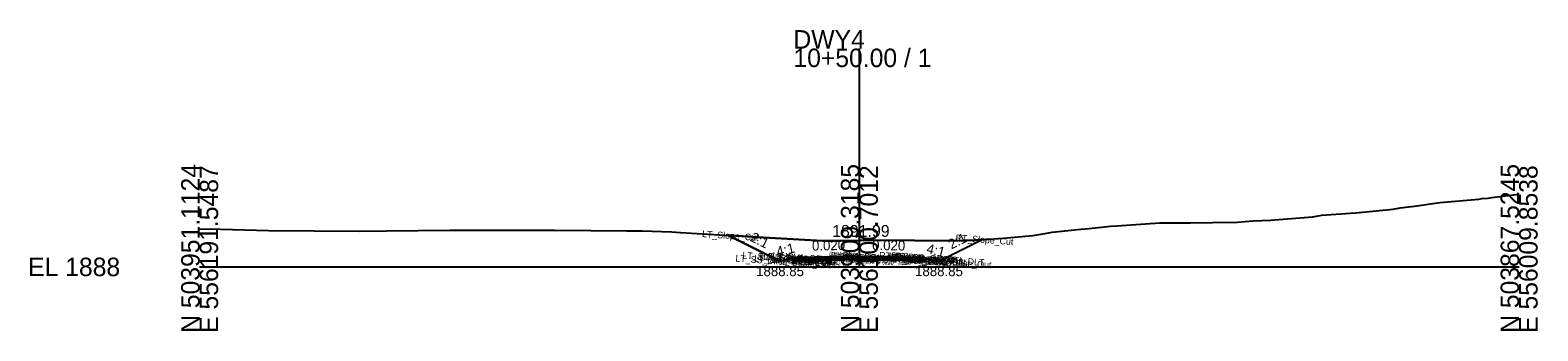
# Model space of a CAD drawing. Extents: x -26 to 556133, y -10 to 503926.
# Drawn here: x -25.7 to 202.8, y 490.3 to 535.9 of the extents above; entities that cross this region are included whole.
import ezdxf

# ---------------------------------------------------------------- set-up
doc = ezdxf.new("R2010")
doc.units = 0
for name, color, linetype in [('Default', 7, 'Continuous'), ('Exist Cross Section Cell', 7, 'Continuous'), ('Exist XS Center Line Elevation Label', 7, 'Continuous'), ('Exist XS Ground Line', 7, 'Continuous'), ('Prop CMT Pvmt Course 1', 7, 'Continuous'), ('Prop CMT Pvmt Course 2', 7, 'Continuous'), ('Prop CMT Pvmt Surface', 7, 'Continuous'), ('Prop CMT Shld Paved Course 1', 7, 'Continuous'), ('Prop CMT Shld Paved Course 2', 7, 'Continuous'), ('Prop CMT Slope Grass', 7, 'Continuous'), ('Prop CMT Subgrade Earthwork', 7, 'Continuous'), ('Prop XS Ditch Standard Text', 7, 'Continuous'), ('Prop XS Earthwork Shape', 7, 'Continuous'), ('Prop XS SE Text', 7, 'Continuous'), ('Prop XS Side Slope Text', 7, 'Continuous'), ('Typical Text Centerline CELL', 7, 'Continuous')]:
    doc.layers.add(name, color=color, linetype=linetype)

msp = doc.modelspace()

# ---------------------------------------------------------------- linework, layer by layer
at = {"layer": 'Exist Cross Section Cell'}
for p, q in [((100, 500), (100, 533.09)), ((0, 500), (100, 500)), ((100, 500), (200, 500))]:
    msp.add_line(p, q, dxfattribs=at)
at = {"layer": 'Exist XS Ground Line'}
for p, q in [((184.12, 509.19), (187.97, 509.76)), ((187.97, 509.76), (193.89, 510.29)), ((193.89, 510.29), (194.35, 510.35)), ((194.35, 510.35), (195.31, 510.43)), ((195.31, 510.43), (195.84, 510.5)), ((195.84, 510.5), (198.31, 510.84)), ((198.31, 510.84), (200, 511.03)), ((164.86, 507.3), (168.73, 507.61)), ((168.73, 507.61), (170.08, 507.83)), ((170.08, 507.83), (174.4, 508.16)), ((174.4, 508.16), (175.25, 508.22)), ((175.25, 508.22), (180.92, 508.77)), ((180.92, 508.77), (181.98, 508.98)), ((181.98, 508.98), (184.12, 509.19)), ((0, 505.76), (3.14, 505.72)), ((3.14, 505.72), (10.42, 505.52)), ((10.42, 505.52), (24.29, 505.44)), ((24.29, 505.44), (28.36, 505.46)), ((28.36, 505.46), (37.92, 505.58)), ((37.92, 505.58), (42.39, 505.58)), ((42.39, 505.58), (53.86, 505.55)), ((53.86, 505.55), (64.73, 505.46)), ((64.73, 505.46), (67.05, 505.46)), ((67.05, 505.46), (71.58, 505.3)), ((71.58, 505.3), (72.89, 505.24)), ((72.89, 505.24), (85.47, 504.46)), ((126.29, 504.74), (128.41, 505.13)), ((128.41, 505.13), (129.2, 505.25)), ((129.2, 505.25), (133.57, 505.7)), ((133.57, 505.7), (134.85, 505.83)), ((134.85, 505.83), (138.06, 506.16)), ((138.06, 506.16), (139.04, 506.23)), ((139.04, 506.23), (145.55, 506.67)), ((145.55, 506.67), (150.18, 506.69)), ((150.18, 506.69), (153.52, 506.72)), ((153.52, 506.72), (157.31, 506.8)), ((157.31, 506.8), (159.64, 506.98)), ((159.64, 506.98), (162.36, 507.1)), ((162.36, 507.1), (164.86, 507.3)), ((85.47, 504.46), (94.39, 503.93)), ((94.39, 503.93), (97.2, 503.95)), ((97.2, 503.95), (100, 503.99)), ((100, 503.99), (102.43, 504.03)), ((102.43, 504.03), (114.33, 503.97)), ((114.33, 503.97), (117.41, 504.05)), ((117.41, 504.05), (121.85, 504.38)), ((121.85, 504.38), (126.29, 504.74))]:
    msp.add_line(p, q, dxfattribs=at)
at = {"layer": 'Prop CMT Pvmt Course 1'}
for points in [[(100, 501.61), (90.95, 501.43)], [(90.95, 501.43), (90.95, 501.18)], [(90.95, 501.18), (100, 501.36)], [(100, 501.36), (100, 501.61)], [(100, 501.61), (109.05, 501.43)], [(100, 501.36), (100, 501.61)], [(109.05, 501.18), (100, 501.36)], [(109.05, 501.43), (109.05, 501.18)]]:
    msp.add_lwpolyline(points, dxfattribs=at)
msp.add_lwpolyline([(100, 501.36), (100, 501.48), (100, 501.48), (100, 501.36)], close=True, dxfattribs=at)
msp.add_lwpolyline([(100, 501.36), (100, 501.48), (100, 501.48), (100, 501.36)], close=True, dxfattribs=at)
at = {"layer": 'Prop CMT Pvmt Course 2'}
for points in [[(100, 501.36), (90.95, 501.18)], [(90.95, 501.18), (90.95, 500.93)], [(90.95, 500.93), (100, 501.11)], [(100, 501.11), (100, 501.36)], [(100, 501.11), (100, 501.36)], [(100, 501.36), (109.05, 501.18)], [(109.05, 500.93), (100, 501.11)], [(109.05, 501.18), (109.05, 500.93)]]:
    msp.add_lwpolyline(points, dxfattribs=at)
at = {"layer": 'Prop CMT Pvmt Surface'}
for points in [[(100, 501.61), (90.95, 501.43)], [(100, 501.61), (109.05, 501.43)]]:
    msp.add_lwpolyline(points, dxfattribs=at)
at = {"layer": 'Prop CMT Shld Paved Course 1'}
for points in [[(90.95, 501.43), (90.7, 501.17)], [(90.7, 501.17), (90.95, 501.18)], [(90.95, 501.18), (90.95, 501.43)], [(109.05, 501.43), (109.3, 501.17)], [(109.05, 501.18), (109.05, 501.43)], [(109.3, 501.17), (109.05, 501.18)]]:
    msp.add_lwpolyline(points, dxfattribs=at)
at = {"layer": 'Prop CMT Shld Paved Course 2'}
for points in [[(90.95, 501.18), (90.7, 501.17), (90.2, 501.16), (89.95, 500.92)], [(89.95, 500.92), (90.95, 500.93)], [(90.95, 500.93), (90.95, 501.18)], [(109.05, 501.18), (109.3, 501.17), (109.8, 501.16), (110.05, 500.92)], [(109.05, 500.93), (109.05, 501.18)], [(110.05, 500.92), (109.05, 500.93)]]:
    msp.add_lwpolyline(points, dxfattribs=at)
at = {"layer": 'Prop CMT Slope Grass'}
for points in [[(90.95, 501.43), (89.95, 501.35), (87.95, 500.85), (80.06, 504.79)], [(109.05, 501.43), (110.05, 501.35), (112.05, 500.85), (118.63, 504.14)]]:
    msp.add_lwpolyline(points, dxfattribs=at)
at = {"layer": 'Prop CMT Subgrade Earthwork'}
for points in [[(90.95, 500.93), (89.95, 500.92), (89.61, 501.26)], [(100, 501.11), (90.95, 500.93)], [(100, 501.11), (109.05, 500.93)], [(109.05, 500.93), (110.05, 500.92), (110.39, 501.26)]]:
    msp.add_lwpolyline(points, dxfattribs=at)
at = {"layer": 'Prop XS Earthwork Shape'}
for points in [[(110.39, 501.26), (112.05, 500.85), (118.63, 504.14), (117.41, 504.05), (114.33, 503.97), (102.43, 504.03), (100, 503.99), (97.2, 503.95), (94.39, 503.93), (85.47, 504.46), (80.06, 504.79), (87.95, 500.85), (89.61, 501.26), (89.95, 501.35), (90.95, 501.43), (100, 501.61), (109.05, 501.43), (110.05, 501.35)], [(100, 501.61), (109.05, 501.43), (110.05, 501.35), (110.39, 501.26), (110.05, 500.92), (109.05, 500.93), (100, 501.11), (90.95, 500.93), (89.95, 500.92), (89.61, 501.26), (89.95, 501.35), (90.95, 501.43)]]:
    msp.add_lwpolyline(points, close=True, dxfattribs=at)

# ---------------------------------------------------------------- texts
at = {"layer": 'Default'}
msp.add_text('-', height=0.0001, dxfattribs=at).set_placement((0, 500))
at = {"layer": 'Exist Cross Section Cell'}
for s, p in [('DWY4', (90, 533.09)), ('10+50.00 / 1', (90, 530.29)), ('EL 1888', (-26, 498.6))]:
    msp.add_text(s, height=2.8, dxfattribs=at).set_placement(p)
for s, p in [('N 503951.1124', (0, 490)), ('E 556191.5487', (2.8, 490)), ('N 503909.3185', (100, 490)), ('E 556100.7012', (102.8, 490)), ('N 503867.5245', (200, 490)), ('E 556009.8538', (202.8, 490))]:
    msp.add_text(s, height=2.8, rotation=90, dxfattribs=at).set_placement(p)
at = {"layer": 'Exist XS Center Line Elevation Label'}
msp.add_text('1891.99', height=1.8, dxfattribs=at).set_placement((95.88, 504.55))
at = {"layer": 'Prop XS Ditch Standard Text'}
for p in [(84.35, 498.6), (108.44, 498.6)]:
    msp.add_text('1888.85', height=1.5, dxfattribs=at).set_placement(p)
at = {"layer": 'Prop XS SE Text'}
for rotation, p in [(1.1458, (92.83, 502.47)), (358.8542, (101.92, 502.57))]:
    msp.add_text('0.020', height=1.5, rotation=rotation, dxfattribs=at).set_placement(p)
at = {"layer": 'Prop XS Side Slope Text'}
for s, rotation, p in [('2:1', 333.4349, (83.33, 504)), ('4:1', 14.0362, (87.62, 501.54)), ('4:1', 345.9638, (110.07, 502.11)), ('2:1', 26.5651, (113.94, 502.63))]:
    msp.add_text(s, height=1.5, rotation=rotation, dxfattribs=at).set_placement(p)
at = {"layer": 'Typical Text Centerline CELL'}
for s, p in [('LT_Slope_Cut', (76.14, 504.53)), ('RT_Slope_Cut', (114.55, 503.92)), ('LT_SS_Ditch_Base_Out', (81.19, 500.82)), ('LT_Sub_Trench_Out_DLT', (82.24, 501.28)), ('LT_Sub_Trench_Out', (84.04, 500.83)), ('LT_PS2_Shelf_Out', (84.84, 501.04)), ('LT_GS_OS_CTL', (85.39, 501.17)), ('LT_PS2_OEOP', (86.46, 500.97)), ('LT_PV2_OEOT', (86.68, 500.98)), ('LT_Sub_OEOT', (86.7, 500.72)), ('LT_PV1_OEOT', (86.8, 501.22)), ('RT_PV2_OEEOP', (95.31, 501.19)), ('RT_Sub_OEEOP', (95.33, 500.93)), ('LT_PV2_OEEOP', (95.37, 501.18)), ('LT_Sub_OEEOP', (95.39, 500.93)), ('RT_PV1_OEEOP', (95.43, 501.3)), ('LT_PV1_OEEOP', (95.49, 501.3)), ('RT_PV2_IEEOP', (95.69, 501.16)), ('LT_PV2_IEEOP', (95.75, 501.15)), ('RT_PV1_IEEOP', (95.81, 501.28)), ('LT_PV1_IEEOP', (95.87, 501.27)), ('PV2_PGL', (97.32, 501.04)), ('PV1_PGL', (97.44, 501.29)), ('RT_Sub_Trench_Out_DLT', (102.96, 501.28)), ('RT_Sub_Trench_Out', (104.07, 500.83)), ('RT_PS2_Shelf_Out', (104.38, 501.04)), ('RT_PV2_OEOT', (104.71, 500.98)), ('RT_Sub_OEOT', (104.73, 500.73)), ('RT_PV1_OEOT', (104.83, 501.22)), ('RT_PS2_OEOP', (105, 500.97)), ('RT_SS_Ditch_Base_Out', (105.22, 500.82)), ('RT_GS_OS_CTL', (105.43, 501.17))]:
    msp.add_text(s, height=1, rotation=356, dxfattribs=at).set_placement(p)

doc.saveas('drawing.dxf')
